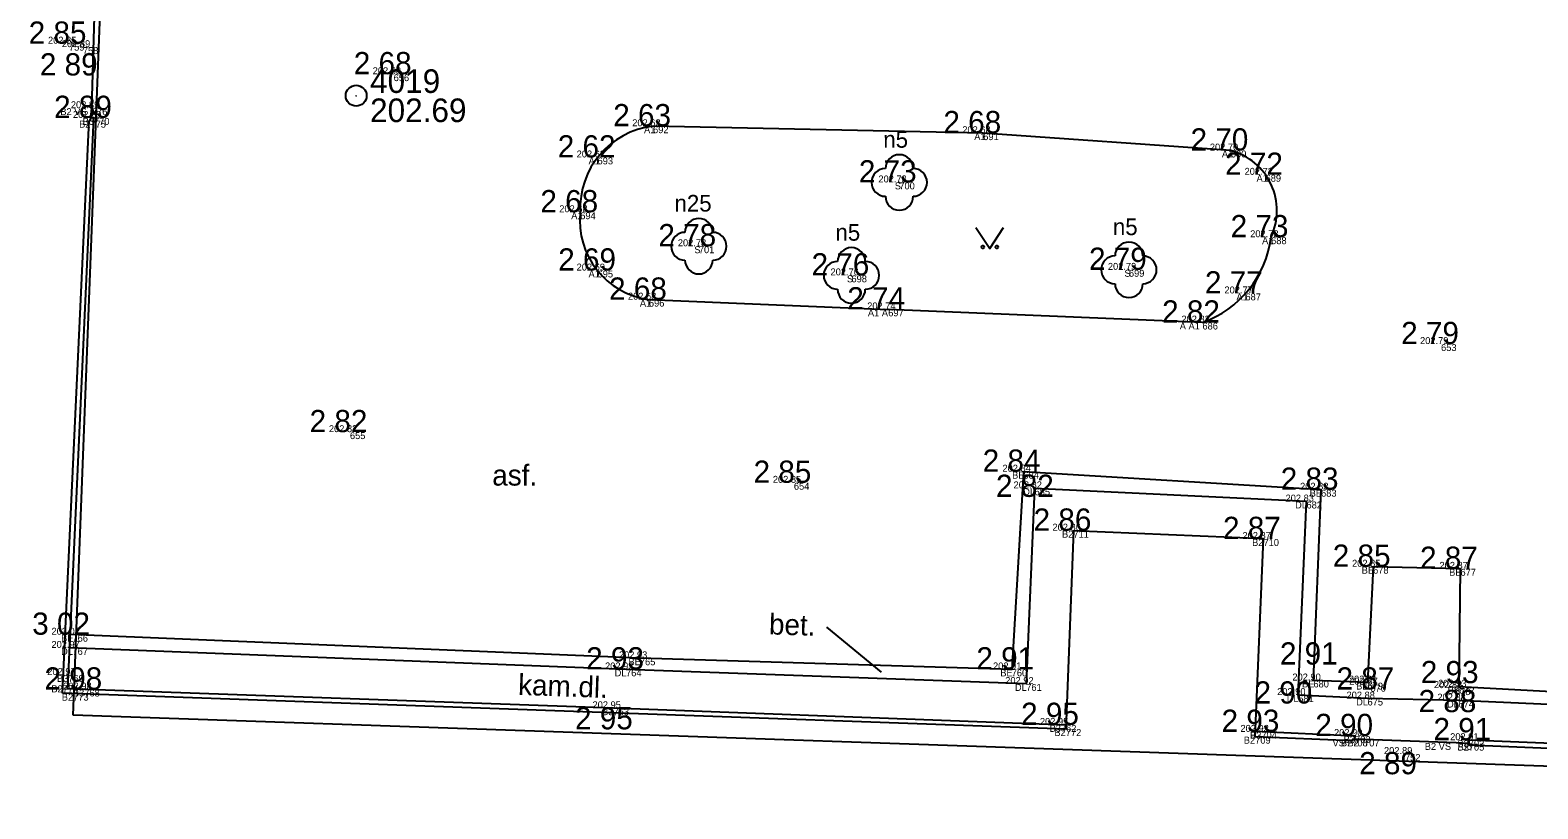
# Model space of a CAD drawing. Extents: x -599717 to -599336, y -1161826 to -1161587.
# Drawn here: x -599564.09 to -599542.35, y -1161716.11 to -1161704.88 of the extents above; entities that cross this region are included whole.
import ezdxf

# ---------------------------------------------------------------- set-up
doc = ezdxf.new("R2010")
doc.units = 0
for name, color, linetype in [('BODY', 7, 'Continuous'), ('BODY_CISLA', 7, 'Continuous'), ('BODY_KODY', 7, 'Continuous'), ('BODY_POLYGONY', 7, 'Continuous'), ('BODY_VYSKY_CELE', 7, 'Continuous'), ('G_BUDOVY', 7, 'Continuous'), ('G_POLOHOPIS', 7, 'Continuous'), ('G_TEXTY', 7, 'Continuous'), ('G_VSTUPY', 7, 'Continuous'), ('G_ZELEN', 7, 'Continuous'), ('G_ZNACKY', 7, 'Continuous'), ('H_KOTY_VYSKOVE', 7, 'Continuous'), ('KN_Vnitřní kresba', 7, 'Continuous')]:
    doc.layers.add(name, color=color, linetype=linetype)

msp = doc.modelspace()

# ---------------------------------------------------------------- linework, layer by layer
at = {"layer": 'BODY'}
for p, q in [((-599563.53, -1161705.08), (-599563.53, -1161705.08)), ((-599563.33, -1161705.13), (-599563.33, -1161705.13)), ((-599558.85, -1161705.52), (-599558.85, -1161705.52)), ((-599563.22, -1161706.19), (-599563.22, -1161706.19)), ((-599563.2, -1161706.01), (-599563.2, -1161706.01)), ((-599563.17, -1161706.15), (-599563.17, -1161706.15)), ((-599555.11, -1161706.27), (-599555.11, -1161706.27)), ((-599550.35, -1161706.37), (-599550.35, -1161706.37)), ((-599546.78, -1161706.62), (-599546.78, -1161706.62)), ((-599555.91, -1161706.72), (-599555.91, -1161706.72)), ((-599546.28, -1161706.97), (-599546.28, -1161706.97)), ((-599551.56, -1161707.08), (-599551.56, -1161707.08)), ((-599556.16, -1161707.51), (-599556.16, -1161707.51)), ((-599546.2, -1161707.87), (-599546.2, -1161707.87)), ((-599554.45, -1161708), (-599554.45, -1161708)), ((-599555.91, -1161708.35), (-599555.91, -1161708.35)), ((-599548.25, -1161708.34), (-599548.25, -1161708.34)), ((-599552.25, -1161708.42), (-599552.25, -1161708.42)), ((-599555.17, -1161708.77), (-599555.17, -1161708.77)), ((-599546.57, -1161708.68), (-599546.57, -1161708.68)), ((-599551.72, -1161708.91), (-599551.72, -1161708.91)), ((-599547.19, -1161709.1), (-599547.19, -1161709.1)), ((-599543.75, -1161709.41), (-599543.75, -1161709.41)), ((-599559.48, -1161710.68), (-599559.48, -1161710.68)), ((-599553.08, -1161711.41), (-599553.08, -1161711.41)), ((-599549.77, -1161711.25), (-599549.77, -1161711.25)), ((-599549.61, -1161711.49), (-599549.61, -1161711.49)), ((-599545.48, -1161711.51), (-599545.48, -1161711.51)), ((-599545.69, -1161711.68), (-599545.69, -1161711.68)), ((-599549.05, -1161712.1), (-599549.05, -1161712.1)), ((-599546.31, -1161712.22), (-599546.31, -1161712.22)), ((-599544.73, -1161712.62), (-599544.73, -1161712.62)), ((-599543.47, -1161712.65), (-599543.47, -1161712.65)), ((-599563.48, -1161713.6), (-599563.48, -1161713.6)), ((-599563.48, -1161713.79), (-599563.48, -1161713.79)), ((-599555.3, -1161713.94), (-599555.3, -1161713.94)), ((-599563.54, -1161714.18), (-599563.54, -1161714.18)), ((-599555.5, -1161714.1), (-599555.5, -1161714.1)), ((-599549.94, -1161714.1), (-599549.94, -1161714.1)), ((-599563.62, -1161714.33), (-599563.62, -1161714.33)), ((-599563.47, -1161714.45), (-599563.47, -1161714.45)), ((-599563.31, -1161714.39), (-599563.31, -1161714.39)), ((-599549.73, -1161714.31), (-599549.73, -1161714.31)), ((-599545.59, -1161714.26), (-599545.59, -1161714.26)), ((-599544.81, -1161714.29), (-599544.81, -1161714.29)), ((-599544.77, -1161714.32), (-599544.77, -1161714.32)), ((-599543.55, -1161714.37), (-599543.55, -1161714.37)), ((-599543.49, -1161714.35), (-599543.49, -1161714.35)), ((-599555.68, -1161714.66), (-599555.68, -1161714.66)), ((-599545.81, -1161714.47), (-599545.81, -1161714.47)), ((-599544.81, -1161714.52), (-599544.81, -1161714.52)), ((-599543.5, -1161714.55), (-599543.5, -1161714.55)), ((-599549.23, -1161714.9), (-599549.23, -1161714.9)), ((-599549.16, -1161714.96), (-599549.16, -1161714.96)), ((-599546.43, -1161715.07), (-599546.43, -1161715.07)), ((-599546.34, -1161715), (-599546.34, -1161715)), ((-599545.03, -1161715.11), (-599545.03, -1161715.11)), ((-599544.99, -1161715.06), (-599544.99, -1161715.06)), ((-599544.86, -1161715.11), (-599544.86, -1161715.11)), ((-599543.35, -1161715.12), (-599543.35, -1161715.12)), ((-599544.27, -1161715.32), (-599544.27, -1161715.32)), ((-599543.53, -1161715.16), (-599543.53, -1161715.16)), ((-599543.35, -1161715.17), (-599543.35, -1161715.17))]:
    msp.add_line(p, q, dxfattribs=at)
at = {"layer": 'BODY_POLYGONY'}
for radius in [0.15, 0.0002]:
    msp.add_circle((-599559.39, -1161705.83), radius, dxfattribs=at)
at = {"layer": 'G_BUDOVY'}
for p, q in [((-599563.22, -1161706.19), (-599563.24, -1161706.189)), ((-599545.03, -1161715.11), (-599545.03, -1161715.11)), ((-599545.03, -1161715.11), (-599545.03, -1161715.13)), ((-599543.35, -1161715.17), (-599543.351, -1161715.19))]:
    msp.add_line(p, q, dxfattribs=at)
for points in [[(-599523.87, -1161696.07), (-599523.89, -1161696.53), (-599527.64, -1161696.43), (-599527.68, -1161697.68), (-599527.75, -1161699.93), (-599524.02, -1161700.04), (-599524.63, -1161715.97), (-599543.351, -1161715.19)], [(-599563.626, -1161714.444), (-599563.24, -1161706.189)], [(-599563.549, -1161714.382), (-599563.17, -1161706.15), (-599563.215, -1161706.148)], [(-599563.22, -1161706.19), (-599563.2, -1161706.01)], [(-599545.03, -1161715.13), (-599546.43, -1161715.07), (-599546.31, -1161712.22), (-599549.05, -1161712.1), (-599549.16, -1161714.96), (-599563.626, -1161714.444)], [(-599549.158, -1161714.903), (-599555.68, -1161714.66), (-599563.549, -1161714.382)], [(-599544.992, -1161715.11), (-599544.99, -1161715.06), (-599546.427, -1161714.996)], [(-599544.86, -1161715.11), (-599545.03, -1161715.11)], [(-599524.683, -1161715.915), (-599525.35, -1161715.85), (-599534.59, -1161715.47), (-599543.35, -1161715.12), (-599543.352, -1161715.17)], [(-599543.35, -1161715.17), (-599543.53, -1161715.16)]]:
    msp.add_lwpolyline(points, dxfattribs=at)
at = {"layer": 'G_POLOHOPIS'}
for points in [[(-599524.802, -1161704.055), (-599525.09, -1161710.66), (-599525.28, -1161715.29), (-599527.56, -1161715.19), (-599532.79, -1161714.97), (-599535.58, -1161714.87), (-599540.26, -1161714.69), (-599543.5, -1161714.55), (-599544.81, -1161714.52), (-599545.81, -1161714.47), (-599545.69, -1161711.68), (-599549.61, -1161711.49), (-599549.73, -1161714.31), (-599555.5, -1161714.1), (-599563.522, -1161713.788)], [(-599546.78, -1161706.62), (-599550.35, -1161706.37), (-599555.11, -1161706.27)], [(-599555.17, -1161708.77), (-599551.72, -1161708.91)], [(-599547.19, -1161709.1), (-599551.72, -1161708.91)], [(-599541.62, -1161714.452), (-599543.49, -1161714.35), (-599543.47, -1161712.65), (-599544.73, -1161712.62), (-599544.81, -1161714.29), (-599545.59, -1161714.26), (-599545.48, -1161711.51), (-599549.77, -1161711.25), (-599549.94, -1161714.1), (-599555.3, -1161713.94), (-599563.513, -1161713.599)]]:
    msp.add_lwpolyline(points, dxfattribs=at)
for centre, radius, start, end in [((-599554.972, -1161707.451), 1.189, 96.661, 182.8249), ((-599547.016, -1161707.489), 0.9, 334.9629, 74.8197), ((-599555.009, -1161707.625), 1.157, 174.3091, 262.0054), ((-599547.705, -1161707.672), 1.518, 289.8351, 352.5052)]:
    msp.add_arc(centre, radius, start, end, dxfattribs=at)
at = {"layer": 'G_TEXTY'}
msp.add_line((-599552.608, -1161713.492), (-599551.824, -1161714.139), dxfattribs=at)
at = {"layer": 'G_VSTUPY'}
for points in [[(-599563.2, -1161706.01), (-599563.16, -1161704.69)], [(-599543.53, -1161715.16), (-599544.86, -1161715.11)]]:
    msp.add_lwpolyline(points, dxfattribs=at)
at = {"layer": 'G_ZELEN'}
for centre in [(-599551.56, -1161707.08), (-599554.45, -1161708), (-599548.25, -1161708.34), (-599552.25, -1161708.42)]:
    msp.add_circle(centre, 0.0002, dxfattribs=at)
for centre, start, end in [((-599551.56, -1161706.88), 0, 180), ((-599551.76, -1161707.08), 90, 270), ((-599551.36, -1161707.08), 270, 90), ((-599551.56, -1161707.28), 180, 360), ((-599554.45, -1161707.8), 0, 180), ((-599554.65, -1161708), 90, 270), ((-599554.25, -1161708), 270, 90), ((-599548.25, -1161708.14), 0, 180), ((-599552.25, -1161708.22), 0, 180), ((-599548.45, -1161708.34), 90, 270), ((-599548.05, -1161708.34), 270, 90), ((-599554.45, -1161708.2), 180, 360), ((-599552.45, -1161708.42), 90, 270), ((-599552.05, -1161708.42), 270, 90), ((-599548.25, -1161708.54), 180, 360), ((-599552.25, -1161708.62), 180, 360)]:
    msp.add_arc(centre, 0.2, start, end, dxfattribs=at)
at = {"layer": 'G_ZNACKY'}
msp.add_lwpolyline([(-599550.456, -1161707.731), (-599550.256, -1161708.031), (-599550.056, -1161707.731)], dxfattribs=at)
for centre in [(-599550.356, -1161708.011), (-599550.156, -1161708.011)]:
    msp.add_circle(centre, 0.02, dxfattribs=at)
at = {"layer": 'KN_Vnitřní kresba'}
for p, q in [((-599563.47, -1161714.76), (-599562.88, -1161699.4)), ((-599524.63, -1161716.11), (-599563.47, -1161714.76))]:
    msp.add_line(p, q, dxfattribs=at)

# ---------------------------------------------------------------- texts
at = {"layer": 'BODY_CISLA'}
for s, p in [('759', (-599563.53, -1161705.18)), ('758', (-599563.33, -1161705.23)), ('656', (-599558.85, -1161705.62)), ('775', (-599563.22, -1161706.29)), ('776', (-599563.2, -1161706.11)), ('770', (-599563.17, -1161706.25)), ('692', (-599555.11, -1161706.37)), ('691', (-599550.35, -1161706.47)), ('690', (-599546.78, -1161706.72)), ('693', (-599555.91, -1161706.82)), ('689', (-599546.28, -1161707.07)), ('700', (-599551.56, -1161707.18)), ('694', (-599556.16, -1161707.61)), ('688', (-599546.2, -1161707.97)), ('701', (-599554.45, -1161708.1)), ('695', (-599555.91, -1161708.45)), ('699', (-599548.25, -1161708.44)), ('698', (-599552.25, -1161708.52)), ('696', (-599555.17, -1161708.87)), ('687', (-599546.57, -1161708.78)), ('697', (-599551.72, -1161709.01)), ('686', (-599547.19, -1161709.2)), ('653', (-599543.75, -1161709.51)), ('655', (-599559.48, -1161710.78)), ('654', (-599553.08, -1161711.51)), ('684', (-599549.77, -1161711.35)), ('685', (-599549.61, -1161711.59)), ('683', (-599545.48, -1161711.61)), ('682', (-599545.69, -1161711.78)), ('711', (-599549.05, -1161712.2)), ('710', (-599546.31, -1161712.32)), ('678', (-599544.73, -1161712.72)), ('677', (-599543.47, -1161712.75)), ('766', (-599563.48, -1161713.7)), ('767', (-599563.48, -1161713.89)), ('765', (-599555.3, -1161714.04)), ('769', (-599563.54, -1161714.28)), ('764', (-599555.5, -1161714.2)), ('760', (-599549.94, -1161714.2)), ('774', (-599563.62, -1161714.43)), ('773', (-599563.47, -1161714.55)), ('768', (-599563.31, -1161714.49)), ('761', (-599549.73, -1161714.41)), ('680', (-599545.59, -1161714.36)), ('679', (-599544.81, -1161714.39)), ('676', (-599544.77, -1161714.42)), ('673', (-599543.55, -1161714.47)), ('672', (-599543.49, -1161714.45)), ('763', (-599555.68, -1161714.76)), ('681', (-599545.81, -1161714.57)), ('675', (-599544.81, -1161714.62)), ('674', (-599543.5, -1161714.65)), ('762', (-599549.23, -1161715)), ('772', (-599549.16, -1161715.06)), ('709', (-599546.43, -1161715.17)), ('704', (-599546.34, -1161715.1)), ('708', (-599545.03, -1161715.21)), ('703', (-599544.99, -1161715.16)), ('707', (-599544.86, -1161715.21)), ('702', (-599543.35, -1161715.22)), ('752', (-599544.27, -1161715.42)), ('706', (-599543.53, -1161715.26)), ('705', (-599543.35, -1161715.27))]:
    msp.add_text(s, height=0.1, dxfattribs=at).set_placement(p)
at = {"layer": 'BODY_KODY'}
for s, p in [('B2 VS', (-599563.655, -1161706.11)), ('B2', (-599563.384, -1161706.29)), ('B3', (-599563.334, -1161706.25)), ('A1', (-599555.24, -1161706.37)), ('A1', (-599550.48, -1161706.47)), ('A1', (-599546.91, -1161706.72)), ('A1', (-599556.04, -1161706.82)), ('A1', (-599546.41, -1161707.07)), ('S', (-599551.625, -1161707.18)), ('A1', (-599556.29, -1161707.61)), ('A1', (-599546.33, -1161707.97)), ('S', (-599554.515, -1161708.1)), ('A1', (-599556.04, -1161708.45)), ('S', (-599548.315, -1161708.44)), ('S', (-599552.315, -1161708.52)), ('A1', (-599555.3, -1161708.87)), ('A1', (-599546.7, -1161708.78)), ('A1 A', (-599552.013, -1161709.01)), ('A A1', (-599547.517, -1161709.2)), ('BE', (-599549.934, -1161711.35)), ('DL', (-599549.774, -1161711.59)), ('BE', (-599545.644, -1161711.61)), ('DL', (-599545.854, -1161711.78)), ('B2', (-599549.214, -1161712.2)), ('B2', (-599546.474, -1161712.32)), ('BE', (-599544.894, -1161712.72)), ('BE', (-599543.634, -1161712.75)), ('BE', (-599563.644, -1161713.7)), ('DL', (-599563.644, -1161713.89)), ('BE', (-599555.464, -1161714.04)), ('B3', (-599563.704, -1161714.28)), ('DL', (-599555.664, -1161714.2)), ('BE', (-599550.104, -1161714.2)), ('B2', (-599563.784, -1161714.43)), ('B2', (-599563.634, -1161714.55)), ('B3', (-599563.474, -1161714.49)), ('DL', (-599549.894, -1161714.41)), ('BE', (-599545.754, -1161714.36)), ('BE', (-599544.974, -1161714.39)), ('BE', (-599543.654, -1161714.45)), ('B3', (-599555.844, -1161714.76)), ('DL', (-599545.974, -1161714.57)), ('DL', (-599544.974, -1161714.62)), ('DL', (-599543.664, -1161714.65)), ('B3', (-599549.394, -1161715)), ('B2', (-599549.324, -1161715.06)), ('B2', (-599546.594, -1161715.17)), ('B3', (-599546.504, -1161715.1)), ('VS B2', (-599545.315, -1161715.21)), ('B2', (-599545.194, -1161715.21)), ('B3', (-599545.154, -1161715.16)), ('B3', (-599543.514, -1161715.22)), ('B2 VS', (-599543.985, -1161715.26)), ('B2', (-599543.514, -1161715.27))]:
    msp.add_text(s, height=0.1, dxfattribs=at).set_placement(p)
at = {"layer": 'BODY_POLYGONY'}
for s, p in [('4019', (-599559.19, -1161705.79)), ('202.69', (-599559.19, -1161706.21))]:
    msp.add_text(s, height=0.34, dxfattribs=at).set_placement(p)
at = {"layer": 'BODY_VYSKY_CELE'}
for s, p in [('202.85 ', (-599563.833, -1161705.08)), ('202.89 ', (-599563.633, -1161705.13)), ('202.68 ', (-599559.152, -1161705.52)), ('202.89 ', (-599563.503, -1161706.01)), ('202.89 ', (-599563.473, -1161706.15)), ('202.63 ', (-599555.41, -1161706.27)), ('202.68 ', (-599550.652, -1161706.37)), ('202.62 ', (-599556.212, -1161706.72)), ('202.70 ', (-599547.083, -1161706.62)), ('202.73 ', (-599551.862, -1161707.08)), ('202.72 ', (-599546.583, -1161706.97)), ('202.68 ', (-599556.462, -1161707.51)), ('202.78 ', (-599554.753, -1161708)), ('202.73 ', (-599546.502, -1161707.87)), ('202.69 ', (-599556.212, -1161708.35)), ('202.76 ', (-599552.552, -1161708.42)), ('202.79 ', (-599548.553, -1161708.34)), ('202.77 ', (-599546.873, -1161708.68)), ('202.68 ', (-599555.472, -1161708.77)), ('202.74 ', (-599552.023, -1161708.91)), ('202.82 ', (-599547.493, -1161709.1)), ('202.79 ', (-599544.053, -1161709.41)), ('202.82 ', (-599559.783, -1161710.68)), ('202.84 ', (-599550.073, -1161711.25)), ('202.85 ', (-599553.383, -1161711.41)), ('202.82 ', (-599549.913, -1161711.49)), ('202.83 ', (-599545.782, -1161711.51)), ('202.83 ', (-599545.992, -1161711.68)), ('202.86 ', (-599549.352, -1161712.1)), ('202.87 ', (-599546.613, -1161712.22)), ('202.85 ', (-599545.033, -1161712.62)), ('202.87 ', (-599543.773, -1161712.65)), ('203.02 ', (-599563.782, -1161713.6)), ('202.97 ', (-599563.783, -1161713.79)), ('202.93 ', (-599555.802, -1161714.1)), ('202.93 ', (-599555.602, -1161713.94)), ('202.91 ', (-599550.209, -1161714.1)), ('202.97 ', (-599563.843, -1161714.18)), ('202.92 ', (-599550.033, -1161714.31)), ('202.90 ', (-599545.893, -1161714.26)), ('202.91 ', (-599545.079, -1161714.29)), ('202.87 ', (-599545.073, -1161714.32)), ('202.93 ', (-599543.792, -1161714.35)), ('202.98 ', (-599563.613, -1161714.39)), ('202.90 ', (-599546.113, -1161714.47)), ('202.88 ', (-599545.113, -1161714.52)), ('202.88 ', (-599543.853, -1161714.37)), ('202.88 ', (-599543.803, -1161714.55)), ('202.95 ', (-599555.983, -1161714.66)), ('202.95 ', (-599549.533, -1161714.9)), ('202.93 ', (-599546.642, -1161715)), ('202.90 ', (-599545.293, -1161715.06)), ('202.91 ', (-599543.619, -1161715.12)), ('202.89 ', (-599544.573, -1161715.32))]:
    msp.add_text(s, height=0.1, dxfattribs=at).set_placement(p)
at = {"layer": 'G_TEXTY'}
for s, height, p in [('n5', 0.24, (-599551.791, -1161706.58)), ('n25', 0.24, (-599554.801, -1161707.5)), ('n5', 0.24, (-599552.481, -1161707.92)), ('n5', 0.24, (-599548.481, -1161707.84)), ('asf.', 0.3, (-599557.428, -1161711.45))]:
    msp.add_text(s, height=height, dxfattribs=at).set_placement(p)
for s, rotation, p in [('bet.', 358.2902, (-599553.442, -1161713.595)), ('kam.dl.', 357.9733, (-599557.059, -1161714.466))]:
    msp.add_text(s, height=0.3, rotation=rotation, dxfattribs=at).set_placement(p)
at = {"layer": 'H_KOTY_VYSKOVE'}
for s, p in [(' 2 85', (-599564.23, -1161705.08)), (' 2 89', (-599564.069, -1161705.538)), (' 2 68', (-599559.543, -1161705.52)), (' 2 89', (-599563.863, -1161706.15)), (' 2 63', (-599555.803, -1161706.27)), (' 2 68', (-599551.043, -1161706.37)), (' 2 62', (-599556.603, -1161706.72)), (' 2 70', (-599547.48, -1161706.62)), (' 2 73', (-599552.262, -1161707.08)), (' 2 72', (-599546.982, -1161706.97)), (' 2 68', (-599556.853, -1161707.51)), (' 2 78', (-599555.152, -1161708)), (' 2 73', (-599546.902, -1161707.87)), (' 2 69', (-599556.596, -1161708.35)), (' 2 76', (-599552.944, -1161708.42)), (' 2 79', (-599548.944, -1161708.34)), (' 2 77', (-599547.273, -1161708.68)), (' 2 68', (-599555.863, -1161708.77)), (' 2 74', (-599552.429, -1161708.91)), (' 2 82', (-599547.89, -1161709.1)), (' 2 79', (-599544.444, -1161709.41)), (' 2 82', (-599560.18, -1161710.68)), (' 2 84', (-599550.477, -1161711.25)), (' 2 85', (-599553.78, -1161711.41)), (' 2 83', (-599546.18, -1161711.51)), (' 2 82', (-599550.285, -1161711.613)), (' 2 86', (-599549.743, -1161712.1)), (' 2 87', (-599547.012, -1161712.22)), (' 2 85', (-599545.43, -1161712.62)), (' 2 87', (-599544.172, -1161712.65)), (' 3 02', (-599564.179, -1161713.6)), (' 2 93', (-599556.193, -1161714.1)), (' 2 91', (-599550.568, -1161714.1)), (' 2 91', (-599546.192, -1161714.03)), (' 2 93', (-599544.161, -1161714.298)), (' 2 98', (-599564.003, -1161714.39)), (' 2 87', (-599545.376, -1161714.39)), (' 2 90', (-599546.558, -1161714.592)), (' 2 88', (-599544.193, -1161714.716)), (' 2 95', (-599556.354, -1161714.964)), (' 2 95', (-599549.923, -1161714.9)), (' 2 93', (-599547.033, -1161715)), (' 2 90', (-599545.682, -1161715.06)), (' 2 91', (-599543.978, -1161715.12)), (' 2 89', (-599545.049, -1161715.611))]:
    msp.add_text(s, height=0.32, dxfattribs=at).set_placement(p)

doc.saveas('drawing.dxf')
